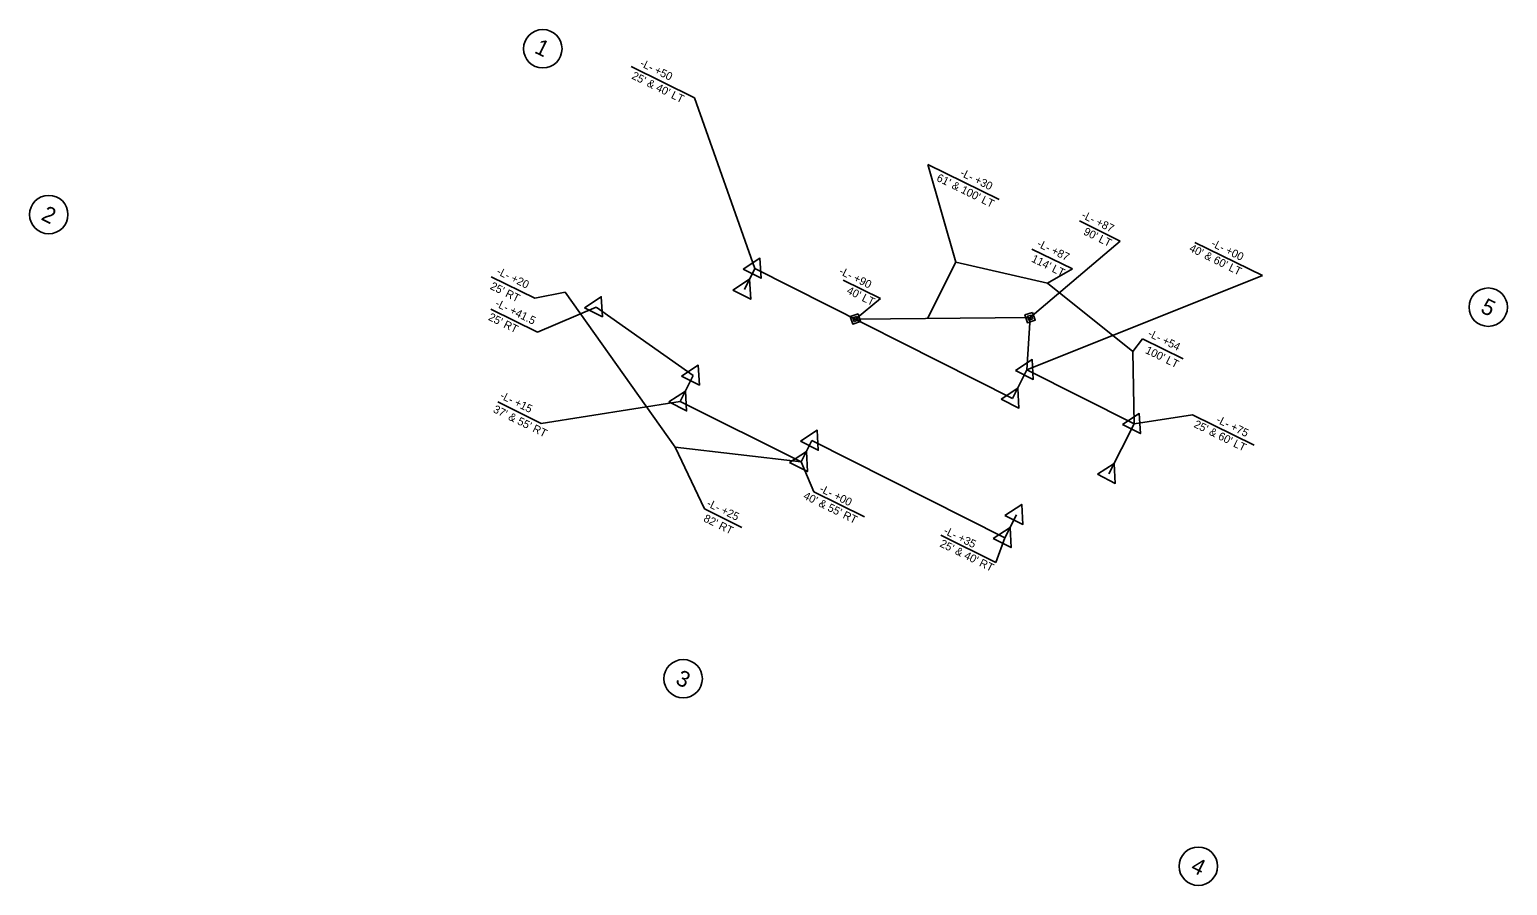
# Model space of a CAD drawing. Extents: x 1429096 to 1430019, y 858353 to 858888.
import ezdxf

# ---------------------------------------------------------------- set-up
doc = ezdxf.new("R2010")
doc.units = 0
for name, color, linetype in [('Prop Easement Construction', 7, 'Continuous'), ('Prop Easement Construction Station Offsets', 7, 'Continuous'), ('Prop Easement Permanent Drainage', 7, 'Continuous'), ('Prop Easement Permanent Drainage Station Offsets', 7, 'Continuous'), ('Prop Parcel Number CELL', 7, 'Continuous'), ('Prop Parcel Number Text', 7, 'Continuous'), ('Prop ROW Marker CELL', 7, 'Continuous'), ('Prop ROW Permanent Easement CELL', 7, 'Continuous'), ('Prop ROW RW Lines', 7, 'Continuous'), ('Prop ROW Station Offsets', 7, 'Continuous')]:
    doc.layers.add(name, color=color, linetype=linetype)

msp = doc.modelspace()

# ---------------------------------------------------------------- linework, layer by layer
at = {"layer": 'Prop Easement Construction'}
for p, q in [((1429656.93, 858707.33), (1429674.68, 858742.48)), ((1429674.68, 858742.48), (1429731.87, 858729.28)), ((1429430.52, 858723.76), (1429499.38, 858626.94)), ((1429731.87, 858729.28), (1429785.36, 858686.58)), ((1429785.36, 858686.58), (1429786.07, 858641.4)), ((1429499.38, 858626.94), (1429578.02, 858617.66))]:
    msp.add_line(p, q, dxfattribs=at)
at = {"layer": 'Prop Easement Construction Station Offsets'}
for p, q in [((1429674.68, 858742.48), (1429657.12, 858803.59)), ((1429701.79, 858781.61), (1429657.12, 858803.59)), ((1429747.49, 858738.22), (1429722.1, 858750.71)), ((1429411.62, 858720), (1429384.4, 858733.39)), ((1429731.87, 858729.28), (1429747.49, 858738.22)), ((1429430.52, 858723.76), (1429411.62, 858720)), ((1429785.36, 858686.58), (1429791.37, 858694.56)), ((1429816.76, 858682.06), (1429791.37, 858694.56)), ((1429499.38, 858626.94), (1429517.56, 858588.26)), ((1429517.56, 858588.26), (1429540.96, 858576.75))]:
    msp.add_line(p, q, dxfattribs=at)
at = {"layer": 'Prop Easement Permanent Drainage'}
for p, q in [((1429611.93, 858706.96), (1429721.05, 858707.86)), ((1429721.05, 858707.86), (1429719.13, 858675.22))]:
    msp.add_line(p, q, dxfattribs=at)
at = {"layer": 'Prop Easement Permanent Drainage Station Offsets'}
for p, q in [((1429751.87, 858768.24), (1429777.37, 858755.69)), ((1429721.05, 858707.86), (1429777.37, 858755.69)), ((1429604.17, 858731.33), (1429627.61, 858719.8)), ((1429611.93, 858706.96), (1429627.61, 858719.8))]:
    msp.add_line(p, q, dxfattribs=at)
at = {"layer": 'Prop Parcel Number CELL'}
for p, q in [((1429416.57, 858875.83), (1429416.57, 858875.83)), ((1429107.84, 858772.22), (1429107.84, 858772.22)), ((1430007.38, 858714.36), (1430007.38, 858714.36)), ((1429504.27, 858482.21), (1429504.27, 858482.21)), ((1429826.21, 858365.04), (1429826.21, 858365.04))]:
    msp.add_line(p, q, dxfattribs=at)
for centre in [(1429416.57, 858875.83), (1429107.84, 858772.22), (1430007.38, 858714.36), (1429504.27, 858482.21), (1429826.21, 858365.04)]:
    msp.add_circle(centre, 12, dxfattribs=at)
at = {"layer": 'Prop ROW Marker CELL'}
for p, q in [((1429549.05, 858738.48), (1429549.05, 858738.48)), ((1429542.56, 858725.35), (1429542.56, 858725.35)), ((1429449.9, 858714.44), (1429449.9, 858714.44)), ((1429611.93, 858706.96), (1429611.93, 858706.96)), ((1429721.05, 858707.86), (1429721.05, 858707.86)), ((1429719.13, 858675.22), (1429719.13, 858675.22)), ((1429510.46, 858671.66), (1429510.46, 858671.66)), ((1429502.49, 858655.52), (1429502.49, 858655.52)), ((1429710.11, 858657.37), (1429710.11, 858657.37)), ((1429786.07, 858641.4), (1429786.07, 858641.4)), ((1429584.78, 858631.04), (1429584.78, 858631.04)), ((1429578.02, 858617.66), (1429578.02, 858617.66)), ((1429770.37, 858610.32), (1429770.37, 858610.32)), ((1429712.6, 858584.65), (1429712.6, 858584.65)), ((1429705.28, 858570.18), (1429705.28, 858570.18))]:
    msp.add_line(p, q, dxfattribs=at)
for points in [[(1429541.85, 858738.09), (1429552.29, 858744.91), (1429553, 858732.45)], [(1429535.35, 858724.96), (1429545.8, 858731.78), (1429546.51, 858719.32)], [(1429442.7, 858714.05), (1429453.14, 858720.87), (1429453.85, 858708.41)], [(1429503.26, 858671.27), (1429513.7, 858678.09), (1429514.41, 858665.63)], [(1429711.93, 858674.82), (1429722.38, 858681.64), (1429723.08, 858669.19)], [(1429495.29, 858655.13), (1429505.74, 858661.95), (1429506.45, 858649.49)], [(1429702.91, 858656.97), (1429713.36, 858663.79), (1429714.07, 858651.34)], [(1429778.87, 858641.01), (1429789.32, 858647.83), (1429790.03, 858635.37)], [(1429577.58, 858630.65), (1429588.03, 858637.47), (1429588.74, 858625.01)], [(1429570.82, 858617.26), (1429581.27, 858624.08), (1429581.98, 858611.62)], [(1429763.17, 858609.92), (1429773.62, 858616.74), (1429774.33, 858604.29)], [(1429705.39, 858584.26), (1429715.84, 858591.08), (1429716.55, 858578.62)], [(1429698.08, 858569.78), (1429708.53, 858576.61), (1429709.24, 858564.15)]]:
    msp.add_lwpolyline(points, close=True, dxfattribs=at)
at = {"layer": 'Prop ROW Permanent Easement CELL'}
for points in [[(1429722.67, 858711.07), (1429724.26, 858706.23), (1429719.43, 858704.64), (1429717.84, 858709.48)], [(1429613.55, 858710.17), (1429615.14, 858705.34), (1429610.3, 858703.75), (1429608.71, 858708.58)], [(1429612.74, 858708.57), (1429613.53, 858706.15), (1429611.11, 858705.35), (1429610.32, 858707.77)], [(1429721.86, 858709.46), (1429722.66, 858707.05), (1429720.24, 858706.25), (1429719.44, 858708.67)]]:
    msp.add_lwpolyline(points, close=True, dxfattribs=at)
at = {"layer": 'Prop ROW RW Lines'}
for p, q in [((1429542.56, 858725.35), (1429549.05, 858738.48)), ((1429549.05, 858738.48), (1429710.11, 858657.37)), ((1429449.9, 858714.44), (1429510.46, 858671.66)), ((1429710.11, 858657.37), (1429719.13, 858675.22)), ((1429719.13, 858675.22), (1429786.07, 858641.4)), ((1429502.49, 858655.52), (1429510.46, 858671.66)), ((1429502.49, 858655.52), (1429578.02, 858617.66)), ((1429770.37, 858610.32), (1429786.07, 858641.4)), ((1429584.78, 858631.04), (1429578.02, 858617.66)), ((1429584.78, 858631.04), (1429705.28, 858570.18)), ((1429705.28, 858570.18), (1429712.6, 858584.65))]:
    msp.add_line(p, q, dxfattribs=at)
at = {"layer": 'Prop ROW Station Offsets'}
for p, q in [((1429511.34, 858845.22), (1429471.83, 858864.66)), ((1429549.05, 858738.48), (1429511.34, 858845.22)), ((1429824.13, 858754.85), (1429866.36, 858734.07)), ((1429719.13, 858675.22), (1429866.36, 858734.07)), ((1429413.26, 858698.84), (1429384.09, 858713.19)), ((1429449.9, 858714.44), (1429413.26, 858698.84)), ((1429502.49, 858655.52), (1429415.65, 858641.78)), ((1429415.65, 858641.78), (1429388.44, 858655.17)), ((1429786.07, 858641.4), (1429822.58, 858647.02)), ((1429822.58, 858647.02), (1429861.11, 858628.06)), ((1429578.02, 858617.66), (1429585.88, 858599.04)), ((1429585.88, 858599.04), (1429617.7, 858583.39)), ((1429699.67, 858554.92), (1429665.34, 858571.81)), ((1429705.28, 858570.18), (1429699.67, 858554.92))]:
    msp.add_line(p, q, dxfattribs=at)

# ---------------------------------------------------------------- texts
at = {"layer": 'Prop Easement Construction Station Offsets'}
for s, p in [("61' & 100' LT", (1429662.18, 858793.53)), ('-L- +30', (1429676.91, 858796.73)), ('-L- +87', (1429724.97, 858752.5)), ("114' LT", (1429721.47, 858743.01)), ("25' RT", (1429383.23, 858725.92)), ('-L- +20', (1429387.27, 858735.18)), ('-L- +54', (1429794.24, 858696.34)), ("100' LT", (1429792.67, 858685.87)), ('-L- +25', (1429518.57, 858590.19)), ("82' RT", (1429516.56, 858580.76))]:
    msp.add_text(s, height=5, rotation=333.80011, dxfattribs=at).set_placement(p)
at = {"layer": 'Prop Easement Permanent Drainage Station Offsets'}
for s, p in [('-L- +87', (1429752.81, 858770.31)), ("90' LT", (1429754.01, 858760)), ('-L- +90', (1429601.29, 858735.29)), ("40' LT", (1429606.02, 858723.19))]:
    msp.add_text(s, height=5, rotation=333.80011, dxfattribs=at).set_placement(p)
at = {"layer": 'Prop Parcel Number Text'}
for s, p in [('1', (1429410.74, 858873.59)), ('2', (1429102.48, 858769.28)), ('5', (1430001.94, 858711.47)), ('3', (1429498.86, 858479.3)), ('4', (1429820.82, 858362.12))]:
    msp.add_text(s, height=10, rotation=333.80011, dxfattribs=at).set_placement(p)
at = {"layer": 'Prop ROW Station Offsets'}
for s, p in [('-L- +50', (1429476.88, 858865.2)), ("25' & 40' LT", (1429471.65, 858857.33)), ("40' & 60' LT", (1429820.05, 858749.63)), ('-L- +00', (1429833.84, 858752.61)), ('-L- +41.5', (1429386.4, 858715.16)), ("25' RT", (1429382.09, 858706.56)), ('-L- +15', (1429389.38, 858657.55)), ("37' & 55' RT", (1429385.08, 858648.95)), ("25' & 60' LT", (1429822.97, 858639.6)), ('-L- +75', (1429836.94, 858642.49)), ('-L- +00', (1429589.03, 858599.29)), ("40' & 55' RT", (1429578.94, 858594.89)), ('-L- +35', (1429666.59, 858573.07)), ("25' & 40' RT", (1429664.23, 858565.02))]:
    msp.add_text(s, height=5, rotation=333.80011, dxfattribs=at).set_placement(p)

doc.saveas('drawing.dxf')
